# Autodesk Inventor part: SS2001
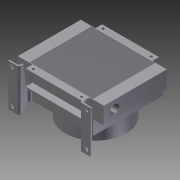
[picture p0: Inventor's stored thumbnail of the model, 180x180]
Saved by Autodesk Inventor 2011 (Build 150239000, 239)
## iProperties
Created: 2011-08
Part Number: SS2001
Document SubType Name: Modeling
Designer: khramov
Density: 1 g/cm^3
Author: khramov
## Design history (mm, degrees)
sketch "Эскиз1"
  geometry: L1 (0, 0)-(318, 0); L2 (318, 0)-(318, -283); L3 (318, -283)-(0, -283); L4 (0, -283)-(0, 0)
  constraints: 8 end point, 2 parallel, 1 horizontal, 1 perpendicular
  dimensions: "d0" = 318 distance of L1.start L1.end; "d1" = 283 distance of L3.end L1.start
extrude "Выдавливание1" new body sketch "Эскиз1" distance "d2" = 63; taper "d3" = 0 deg
sketch "Эскиз2"
  geometry: L1 (-63, 283)-(-63, 0) reference; L2 (0, 283)-(0, 0) reference; L3 (0, 283)-(-63, 283) reference; L4 (-58, 283)-(-5, 283); L5 (-5, 283)-(-5, 258); L6 (-5, 258)-(-58, 258); L7 (-58, 258)-(-58, 283); L8 (-63, 0)-(-63, 283) reference; L9 (-63, 141.5)-(63.697, 141.5); L10 (0, 0)-(-63, 0); L11 (-58, 0)-(-5, 0); L12 (-5, 0)-(-5, 25); L13 (-5, 25)-(-58, 25); L14 (-58, 25)-(-58, 0)
  constraints: 20 end point, 4 symmetric about line, 2 parallel, 2 perpendicular, 2 point on line, 1 horizontal, 1 midpoint
  dimensions: "d4" = 5 distance between parallel lines of L7 L1; "d5" = 5 distance between parallel lines of L2 L5; "d6" = 25 distance between parallel lines of L3 L6
extrude "Выдавливание2" cut sketch "Эскиз2" stored distance "d7" = 63; taper "d8" = 0 deg
sketch "Эскиз3"
  geometry: L1 (0, 0)-(54, 0); L2 (54, 0)-(54, -25); L3 (54, -25)-(0, -25); L4 (0, -25)-(0, 0); L5 (318, 0)-(264, 0); L6 (264, 0)-(264, -25); L7 (264, -25)-(318, -25); L8 (318, -25)-(318, 0); L9 (0, -141.5)-(444.092, -141.5); L10 (0, -283)-(54, -283); L11 (54, -283)-(54, -258); L12 (54, -258)-(0, -258); L13 (0, -258)-(0, -283); L14 (318, -283)-(264, -283); L15 (264, -283)-(264, -258); L16 (264, -258)-(318, -258); L17 (318, -258)-(318, -283)
  constraints: 34 end point, 8 symmetric about line, 4 parallel, 3 perpendicular, 2 horizontal
  dimensions: "d9" = 25 distance of L1.end L2.end; "d10" = 25 distance of L5.end L6.end; "d11" = 210 distance between parallel lines of L6 L2; "d13" = 54 distance of L2.end L3.end
extrude "Выдавливание3" cut sketch "Эскиз3" stored distance "d14" = 0; taper "d15" = 0 deg
sketch "Эскиз4"
  geometry: L1 (54, 0)-(54, -25) reference; L2 (54, 0)-(264, 0) reference; L3 (70, -12.5)-(248, -12.5); L4 (248, -12.5)-(248, -270.5); L5 (248, -270.5)-(70, -270.5); L6 (70, -270.5)-(70, -12.5); C1 r 4.5 at (70, -12.5); C2 r 4.5 at (248, -12.5); C3 r 4.5 at (248, -270.5); C4 r 4.5 at (70, -270.5); 1 further point
  constraints: 8 end point, 4 centre point, 4 coincident, 2 parallel, 1 horizontal, 1 perpendicular
  dimensions: "d16" = 9 diameter of C1; "d17" = 9 diameter of C2; "d18" = 9 diameter of C3; "d19" = 9 diameter of C4; "d20" = 258 distance of L5.end L3.start; "d21" = 178 distance of L3.start L3.end; "d22" = 16 distance between parallel lines of L6 L1; "d23" = 12.5 distance between parallel lines of L3 L2
extrude "Выдавливание4" cut sketch "Эскиз4" distance "d24" = 10; taper "d25" = 0 deg
sketch "Эскиз5"
  geometry: L1 (54, 0)-(54, -25) reference; L2 (54, -25)-(0, -25) reference; L3 (0, -258)-(54, -258) reference; L4 (264, -25)-(264, 0) reference; L5 (42, -27)-(276, -27); L6 (276, -27)-(276, -256); L7 (276, -256)-(42, -256); L8 (42, -256)-(42, -27); 1 further point
  constraints: 8 end point, 2 parallel, 1 horizontal, 1 perpendicular
  dimensions: "d26" = 2 distance between parallel lines of L5 L2; "d27" = 2 distance between parallel lines of L3 L7; "d28" = 12 distance between parallel lines of L1 L8; "d29" = 12 distance between parallel lines of L6 L4
extrude "Выдавливание5" cut sketch "Эскиз5" distance "d30" = 2; taper "d31" = 0 deg
sketch "Эскиз6"
  geometry: L1 (-264, 0)-(-264, -25) reference; L2 (-279, 0)-(-39, 0); L3 (-39, 0)-(-39, -258); L4 (-39, -258)-(-279, -258); L5 (-279, -258)-(-279, 0); 1 further point
  constraints: 8 end point, 2 parallel, 1 horizontal, 1 perpendicular
  dimensions: "d32" = 210 distance of point (-54, 0) L1.start (derived); "d33" = 240 distance between parallel lines of L3 L5; "d34" = 15 distance between parallel lines of L1 L5; "d35" = 258 distance of L4.end L2.start
extrude "Выдавливание6" join sketch "Эскиз6" distance "d36" = 53; taper "d37" = 0 deg
sketch "Эскиз7"
  geometry: L1 (-279, 0)-(-39, -258); L2 (-39, 0)-(-279, -258); C1 r 112.5 at (-159, -129); 1 further point
  constraints: 4 end point, 1 centre point, 1 midpoint
  dimensions: "d38" = 225 diameter of C1
extrude "Выдавливание7" join sketch "Эскиз7" distance "d39" = 60; taper "d40" = 0 deg
sketch "Эскиз8"
  geometry: L1 (-276.5, -265)-(-276.5, -288); L2 (-283.5, -295)-(-311.5, -295); L3 (-311.5, -295)-(-311.5, -300); L4 (-311.5, -300)-(-278.5, -300); L5 (-271.5, -293)-(-271.5, -270); L6 (-264.5, -263)-(-264, -263); L7 (-264, -258)-(-264, -263); L8 (-269.5, -258)-(-264, -258); L9 (-159, -129)-(-159, -359.645); L10 (-296.5, -281.5)-(-296.5, -330.929); L11 (-41.5, -265)-(-41.5, -288); L12 (-46.5, -293)-(-46.5, -270); L13 (-6.5, -300)-(-39.5, -300); L14 (-34.5, -295)-(-6.5, -295); L15 (-21.5, -281.5)-(-21.5, -330.929); L16 (-6.5, -295)-(-6.5, -300); L17 (-53.5, -263)-(-54, -263); L18 (-54, -258)-(-54, -263); L19 (-48.5, -258)-(-54, -258); A1 r 7 centre (-283.5, -288) between (-283.5, -295) and (-276.5, -288); A2 r 7 centre (-278.5, -293) between (-278.5, -300) and (-271.5, -293); A3 r 7 centre (-264.5, -270) between (-264.5, -263) and (-271.5, -270); A4 r 7 centre (-269.5, -265) between (-269.5, -258) and (-276.5, -265); A5 r 7 centre (-39.5, -293) between (-46.5, -293) and (-39.5, -300); A6 r 7 centre (-34.5, -288) between (-41.5, -288) and (-34.5, -295); A7 r 7 centre (-53.5, -270) between (-46.5, -270) and (-53.5, -263); A8 r 7 centre (-48.5, -265) between (-41.5, -265) and (-48.5, -258); 2 further points
  constraints: 38 end point, 19 symmetric about line, 16 point on circle, 8 centre point, 8 tangent, 4 parallel, 4 point on line, 3 equal radius, 1 perpendicular, 4 other
  dimensions: "d41" = 5 distance of L2.end L3.end; "d42" = 5 distance between parallel lines of L1 L5; "d43" = 5 distance between parallel lines of L6 L8; "d45" = 35 distance of point (-276.5, -295) L2.end; "d46" = 15 distance between parallel lines of L10 L3; "d47" = 20 distance between parallel lines of L1 L10 (derived); "d48" = 7 radius of A1; "d49" = 275 distance between parallel lines of L15 L10
extrude "Выдавливание8" join sketch "Эскиз8" distance "d50" = 30; taper "d52" = 0 deg; dims "d51" = 126, "d53" = 0
sketch "Эскиз9"
  geometry: L1 (-30, 42)-(-27.687, 27.383); L2 (-27.687, 27.383)-(0, 12.765); L3 (0, 30)-(0, 7) reference; L4 (0, 42)-(0, 12.765); L5 (-30, 42)-(0, 42); L6 (0, 42)-(-30, 42) reference; L7 (-30, 42)-(-83, 42) reference; L8 (-67.613, 42)-(-67.613, 27.383); L9 (0, 30)-(-156, 30) reference; L10 (-67.613, 27.383)-(-156, 17); L11 (-156, 7)-(-156, 30) reference; L12 (-156, 42)-(-67.613, 42); L13 (0, 37)-(-156, 37) reference; L14 (-156, 42)-(-156, 17); 1 further point
  constraints: 16 end point, 3 collinear, 3 point on line, 1 parallel, 1 perpendicular
extrude "Выдавливание9" cut sketch "Эскиз9" stored distance "d54" = 60; taper "d55" = 0 deg
sketch "Эскиз10"
  geometry: L1 (-10, 5)-(-10, 0) reference; L2 (78.387, 5)-(78.387, -9.617); L3 (78.387, -2)-(78.387, 5) reference; L4 (78.387, -9.617)-(-10, -20); L5 (78.387, -9.617)-(-10, -20) reference; L6 (-10, -20)-(-10, 5); L7 (78.387, 5)-(-10, 5); L8 (116, 5)-(118.313, -9.617); L9 (118.313, -9.617)-(117.108, -2) reference; L10 (118.313, -9.617)-(146, -25); L11 (146, -25)-(146, 5); L12 (146, -25)-(-10, -25) reference; L13 (146, 5)-(116, 5); 1 further point
  constraints: 16 end point, 3 collinear, 2 perpendicular, 1 parallel
extrude "Выдавливание10" cut sketch "Эскиз10" distance "d56" = 60; taper "d57" = 0 deg
sketch "Эскиз11"
  geometry: L1 (33, 0)-(33, 156) reference; L2 (18, 143)-(-257, 143); L3 (-257, 143)-(-257, 17); L4 (-257, 17)-(18, 17); L5 (18, 17)-(18, 143); L6 (-14.5, 146)-(-224.5, 146) reference; C1 r 6.5 at (18, 143); C2 r 6.5 at (18, 17); C3 r 6.5 at (-257, 17); C4 r 6.5 at (-257, 143); 1 further point
  constraints: 8 end point, 4 centre point, 4 coincident, 2 parallel, 1 horizontal, 1 perpendicular
  dimensions: "d58" = 13 diameter of C2; "d59" = 13 diameter of C1; "d60" = 13 diameter of C3; "d61" = 13 diameter of C4; "d62" = 275 distance of L2.start L2.end; "d63" = 126 distance of L4.end L2.start; "d64" = 3 distance from line of L6 C1.centre; "d65" = 15 distance from line of C1.centre L1
extrude "Выдавливание11" cut sketch "Эскиз11" distance "d66" = 10; taper "d67" = 0 deg
sketch "Эскиз12"
  geometry: L1 (-63, 0)-(0, 0) reference; L2 (-63, 233)-(-63, 0) reference; L3 (-31.5, 0)-(-31.5, 41.5); L4 (83, -42)-(-73, -42) reference; 2 further points
  constraints: 2 end point, 1 coincident, 1 midpoint, 1 parallel
  dimensions: "d69" = 83.5 distance from line of point (-31.5, 41.5) L4
hole "Отверстие1" sketch "Эскиз12" at (-31.5, 41.5) diameter "d70" = 30.291; stored, may be unused: countersink angle "d74" = 90 deg, drill point angle "d76" = 118 deg; dims "d71" = 40, "d72" = 34, "d73" = 2, "d75" = 50
sketch "Эскиз13"
  geometry: L1 (0, 233)-(63, 233) reference; L2 (31.5, 233)-(31.5, 198.5); C1 r 15.146 at (31.5, 41.5) reference; 2 further points
  constraints: 2 end point, 1 coincident, 1 midpoint, 1 perpendicular
  dimensions: "d77" = 157 distance of C1.centre point (31.5, 198.5)
hole "Отверстие2" sketch "Эскиз13" at (31.5, 198.5) diameter "d78" = 30.291; stored, may be unused: countersink angle "d82" = 90 deg, drill point angle "d84" = 118 deg; dims "d79" = 40, "d80" = 34, "d81" = 2, "d83" = 50
node "Твердое тело1"
